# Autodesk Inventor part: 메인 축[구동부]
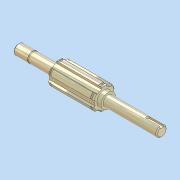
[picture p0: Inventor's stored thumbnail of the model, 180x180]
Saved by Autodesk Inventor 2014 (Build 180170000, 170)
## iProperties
Company: 한국ATC센터
Created: 2012-05
Part Number: 메인 축[구동부]
Document SubType Name: 모델링
Designer: KYOUNG IL JANG
Mass: 168.566 g
Surface Area: 72.5104 cm^2
Volume: 21.4461 cm^3
Density: 7.86 g/cm^3
Material: 강, 연강
Appearance: 강철
변환 표준: STEP AP214IS
파일 이름: C:\Users\SeoGD\Desktop\?쒗뿕\硫붿씤 異?.stp
전처리기: Build: 253, Release: 2010 SP1 - Date: Wed 07/29/2009
전송 단위: 밀리미터
불확실성: 0.01
Author: KYOUNG IL JANG
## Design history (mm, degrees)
sketch "스케치1"
  geometry: L1 (-69.5, 0)-(69.5, 0); L2 (69.5, 0)-(69.5, 5); L3 (69.5, 5)-(55.5, 5); L4 (55.5, 5)-(55.5, 4.8); L5 (55.5, 4.8)-(54.35, 4.8); L6 (54.35, 4.8)-(54.35, 5); L7 (54.35, 5)-(30.5, 5); L8 (30.5, 5)-(30.5, 9); L9 (30.5, 9)-(-13.5, 9); L10 (-13.5, 9)-(-13.5, 7); L11 (-13.5, 7)-(-17.5, 7); L12 (-17.5, 7)-(-17.5, 5); L13 (-17.5, 5)-(-69.5, 5); L14 (-69.5, 5)-(-69.5, 0); 2 further points
  constraints: 28 end point, 9 parallel, 4 collinear, 2 perpendicular, 1 coincident, 1 horizontal, 1 midpoint
  dimensions: "d2" = 1.15 distance between parallel lines of L6 L4; "d3" = 10 diameter of L3 L1; "d4" = 9.6 diameter of L5 L1; "d6" = 44 distance between parallel lines of L10 L8; "d7" = 4 distance between parallel lines of L12 L10; "d8" = 14 diameter of L11 L1; "d9" = 18 diameter of L9 L1; "d33" = 52 distance from line of L12.end L14; "d37" = 39 distance between parallel lines of L8 L2; "d38" = 14 distance between parallel lines of L2 L4
revolve "회전1" sketch "스케치1" stored, may be unused: angle "d10" = 90 deg
sketch "스케치2"
  geometry: L1 (2.5, 10.712)-(2.5, 8.646); L2 (-2.5, 10.712)-(-2.5, 8.646); A1 r 9 centre (0, 0) between (2.5, 8.646) and (-2.5, 8.646) reference; A2 r 11 centre (0, 0) between (2.5, 10.712) and (-2.5, 10.712); 1 further point
  constraints: 4 end point, 4 point on circle, 2 parallel, 1 centre point, 1 coincident, 1 vertical
  dimensions: "d11" = 22 diameter of A2; "d12" = 5 distance between parallel lines of L1 L2
extrude "돌출1" join sketch "스케치2" stored distance "d13" = 10; taper "d14" = 0 deg
chamfer "모따기1" distance "d15" = 1; stored, may be unused: second distance "d16" = 2, angle "d17" = 45 deg
node "작업 평면1"
node "작업 평면2"
sketch "스케치3"
  geometry: L1 (2.5, 10.712)-(2.5, 10.198); L2 (-2.5, 10.712)-(-2.5, 10.198); A1 r 11 centre (0, 0) between (2.5, 10.712) and (-2.5, 10.712) reference; A2 r 10.5 centre (0, 0) between (2.5, 10.198) and (-2.5, 10.198); 1 further point
  constraints: 4 end point, 2 point on circle, 1 centre point, 1 coincident, 1 parallel, 1 vertical
  dimensions: "d19" = 21 diameter of A2
extrude "돌출2" cut sketch "스케치3" distance "d20" = 1.35; taper "d21" = 0 deg
node "작업 평면3"
sketch "스케치4"
  geometry: L1 (-26, -5)-(-26, 5) reference; L2 (-26, 1.5)-(-12.5, 1.5); L3 (-12.5, -1.5)-(-26, -1.5); A1 r 1.5 centre (-12.5, 0) between (-12.5, -1.5) and (-12.5, 1.5); 2 further points
  constraints: 4 end point, 2 perpendicular, 2 point on circle, 2 point on line, 2 tangent, 1 centre point, 1 horizontal alignment, 1 midpoint
  dimensions: "d25" = 3 distance between parallel lines of L3 L2; "d26" = 15 dimension on A1 L1
extrude "돌출3" cut sketch "스케치4" distance "d27" = 1.8; taper "d28" = 0 deg
chamfer "모따기2" distance "d29" = 1; stored, may be unused: second distance "d30" = 2, angle "d31" = 45 deg
node "솔리드1"
node "솔리드 본체"
node "곡면 본체"
mirror "대칭1"
pattern_circular "원형 패턴1" dims "d23" = 360 deg
node "솔리드2"
other parameters: "d18" = -1.65
